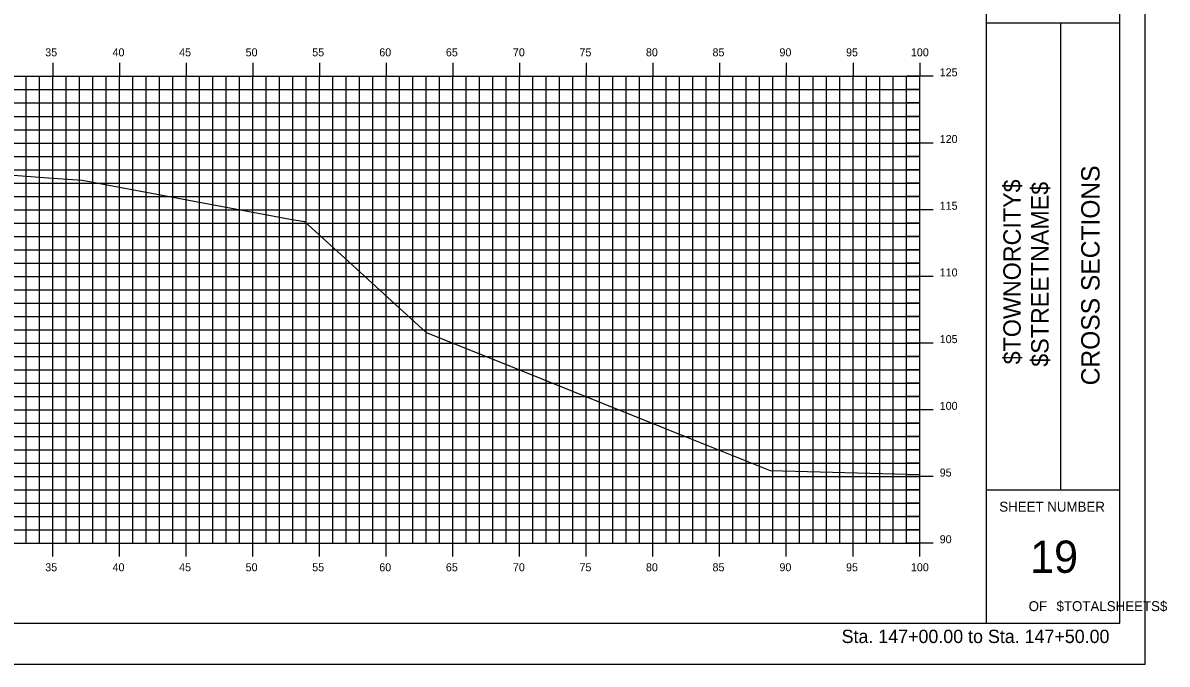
# Model space of a CAD drawing. Extents: x 850598 to 870284, y 366541 to 366651.
# Drawn here: x 850683.7 to 850769.4, y 366541.2 to 366589.2 of the extents above; entities that cross this region are included whole.
import ezdxf

# ---------------------------------------------------------------- set-up
doc = ezdxf.new("R2010")
doc.units = 0
for name, color, linetype in [('BORDER', 7, 'Continuous'), ('H_V ANNOTATION', 7, 'Continuous'), ('HIGHWAY_TITLE', 7, 'Continuous'), ('MAJOR', 7, 'Continuous'), ('MINOR', 7, 'Continuous'), ('PLOT BOUNDARY', 7, 'Continuous'), ('S_Roadway_Centerline', 7, 'Continuous')]:
    doc.layers.add(name, color=color, linetype=linetype)

msp = doc.modelspace()

# ---------------------------------------------------------------- linework, layer by layer
at = {"layer": 'BORDER'}
for p, q in [((850755.897, 366544.225), (850755.897, 366649.225)), ((850765.897, 366544.225), (850765.897, 366649.225)), ((850755.897, 366589.228), (850765.897, 366589.228)), ((850761.488, 366554.228), (850761.488, 366589.228)), ((850755.897, 366554.228), (850765.897, 366554.228)), ((850605.897, 366544.225), (850765.897, 366544.225))]:
    msp.add_line(p, q, dxfattribs=at)
at = {"layer": 'MAJOR'}
for p, q in [((850685.897, 366586.227), (850685.897, 366585.225)), ((850685.897, 366586.227), (850685.897, 366585.225)), ((850690.897, 366586.227), (850690.897, 366585.225)), ((850690.897, 366586.227), (850690.897, 366585.225)), ((850695.897, 366586.227), (850695.897, 366585.225)), ((850695.897, 366586.227), (850695.897, 366585.225)), ((850700.897, 366586.227), (850700.897, 366585.225)), ((850700.897, 366586.227), (850700.897, 366585.225)), ((850705.897, 366586.227), (850705.897, 366585.225)), ((850705.897, 366586.227), (850705.897, 366585.225)), ((850710.897, 366586.227), (850710.897, 366585.225)), ((850710.897, 366586.227), (850710.897, 366585.225)), ((850715.897, 366586.227), (850715.897, 366585.225)), ((850715.897, 366586.227), (850715.897, 366585.225)), ((850720.897, 366586.227), (850720.897, 366585.225)), ((850720.897, 366586.227), (850720.897, 366585.225)), ((850725.897, 366586.227), (850725.897, 366585.225)), ((850725.897, 366586.227), (850725.897, 366585.225)), ((850730.897, 366586.227), (850730.897, 366585.225)), ((850730.897, 366586.227), (850730.897, 366585.225)), ((850735.897, 366586.227), (850735.897, 366585.225)), ((850735.897, 366586.227), (850735.897, 366585.225)), ((850740.897, 366586.227), (850740.897, 366585.225)), ((850740.897, 366586.227), (850740.897, 366585.225)), ((850745.897, 366586.227), (850745.897, 366585.225)), ((850745.897, 366586.227), (850745.897, 366585.225)), ((850750.897, 366586.227), (850750.897, 366585.225)), ((850750.897, 366586.227), (850750.897, 366585.225)), ((850610.897, 366585.225), (850750.897, 366585.225)), ((850610.897, 366585.225), (850750.897, 366585.225)), ((850610.897, 366585.225), (850750.897, 366585.225)), ((850610.897, 366585.225), (850750.897, 366585.225)), ((850685.897, 366550.225), (850685.897, 366585.225)), ((850685.897, 366550.225), (850685.897, 366585.225)), ((850690.897, 366550.225), (850690.897, 366585.225)), ((850690.897, 366550.225), (850690.897, 366585.225)), ((850695.897, 366550.225), (850695.897, 366585.225)), ((850695.897, 366550.225), (850695.897, 366585.225)), ((850700.897, 366550.225), (850700.897, 366585.225)), ((850700.897, 366550.225), (850700.897, 366585.225)), ((850705.897, 366550.225), (850705.897, 366585.225)), ((850705.897, 366550.225), (850705.897, 366585.225)), ((850710.897, 366550.225), (850710.897, 366585.225)), ((850710.897, 366550.225), (850710.897, 366585.225)), ((850715.897, 366550.225), (850715.897, 366585.225)), ((850715.897, 366550.225), (850715.897, 366585.225)), ((850720.897, 366550.225), (850720.897, 366585.225)), ((850720.897, 366550.225), (850720.897, 366585.225)), ((850725.897, 366550.225), (850725.897, 366585.225)), ((850725.897, 366550.225), (850725.897, 366585.225)), ((850730.897, 366550.225), (850730.897, 366585.225)), ((850730.897, 366550.225), (850730.897, 366585.225)), ((850735.897, 366550.225), (850735.897, 366585.225)), ((850735.897, 366550.225), (850735.897, 366585.225)), ((850740.897, 366550.225), (850740.897, 366585.225)), ((850740.897, 366550.225), (850740.897, 366585.225)), ((850745.897, 366550.225), (850745.897, 366585.225)), ((850745.897, 366550.225), (850745.897, 366585.225)), ((850751.899, 366585.225), (850749.895, 366585.225)), ((850751.899, 366585.225), (850749.895, 366585.225)), ((850750.897, 366550.225), (850750.897, 366585.225)), ((850750.897, 366550.225), (850750.897, 366585.225)), ((850750.897, 366550.225), (850750.897, 366585.225)), ((850750.897, 366550.225), (850750.897, 366585.225)), ((850610.897, 366580.225), (850750.897, 366580.225)), ((850610.897, 366580.225), (850750.897, 366580.225)), ((850751.899, 366580.225), (850749.895, 366580.225)), ((850751.899, 366580.225), (850749.895, 366580.225)), ((850610.897, 366575.225), (850750.897, 366575.225)), ((850610.897, 366575.225), (850750.897, 366575.225)), ((850751.899, 366575.225), (850749.895, 366575.225)), ((850751.899, 366575.225), (850749.895, 366575.225)), ((850610.897, 366570.225), (850750.897, 366570.225)), ((850610.897, 366570.225), (850750.897, 366570.225)), ((850751.899, 366570.225), (850749.895, 366570.225)), ((850751.899, 366570.225), (850749.895, 366570.225)), ((850610.897, 366565.225), (850750.897, 366565.225)), ((850610.897, 366565.225), (850750.897, 366565.225)), ((850751.899, 366565.225), (850749.895, 366565.225)), ((850751.899, 366565.225), (850749.895, 366565.225)), ((850610.897, 366560.225), (850750.897, 366560.225)), ((850610.897, 366560.225), (850750.897, 366560.225)), ((850751.899, 366560.225), (850749.895, 366560.225)), ((850751.899, 366560.225), (850749.895, 366560.225)), ((850610.897, 366555.225), (850750.897, 366555.225)), ((850610.897, 366555.225), (850750.897, 366555.225)), ((850751.899, 366555.225), (850749.895, 366555.225)), ((850751.899, 366555.225), (850749.895, 366555.225)), ((850610.897, 366550.225), (850750.897, 366550.225)), ((850610.897, 366550.225), (850750.897, 366550.225)), ((850610.897, 366550.225), (850750.897, 366550.225)), ((850610.897, 366550.225), (850750.897, 366550.225)), ((850685.897, 366549.223), (850685.897, 366550.225)), ((850685.897, 366549.223), (850685.897, 366550.225)), ((850690.897, 366549.223), (850690.897, 366550.225)), ((850690.897, 366549.223), (850690.897, 366550.225)), ((850695.897, 366549.223), (850695.897, 366550.225)), ((850695.897, 366549.223), (850695.897, 366550.225)), ((850700.897, 366549.223), (850700.897, 366550.225)), ((850700.897, 366549.223), (850700.897, 366550.225)), ((850705.897, 366549.223), (850705.897, 366550.225)), ((850705.897, 366549.223), (850705.897, 366550.225)), ((850710.897, 366549.223), (850710.897, 366550.225)), ((850710.897, 366549.223), (850710.897, 366550.225)), ((850715.897, 366549.223), (850715.897, 366550.225)), ((850715.897, 366549.223), (850715.897, 366550.225)), ((850720.897, 366549.223), (850720.897, 366550.225)), ((850720.897, 366549.223), (850720.897, 366550.225)), ((850725.897, 366549.223), (850725.897, 366550.225)), ((850725.897, 366549.223), (850725.897, 366550.225)), ((850730.897, 366549.223), (850730.897, 366550.225)), ((850730.897, 366549.223), (850730.897, 366550.225)), ((850735.897, 366549.223), (850735.897, 366550.225)), ((850735.897, 366549.223), (850735.897, 366550.225)), ((850740.897, 366549.223), (850740.897, 366550.225)), ((850740.897, 366549.223), (850740.897, 366550.225)), ((850745.897, 366549.223), (850745.897, 366550.225)), ((850745.897, 366549.223), (850745.897, 366550.225)), ((850751.899, 366550.225), (850749.895, 366550.225)), ((850751.899, 366550.225), (850749.895, 366550.225)), ((850750.897, 366549.223), (850750.897, 366550.225)), ((850750.897, 366549.223), (850750.897, 366550.225))]:
    msp.add_line(p, q, dxfattribs=at)
at = {"layer": 'MINOR'}
for p, q in [((850683.897, 366550.225), (850683.897, 366585.225)), ((850683.897, 366550.225), (850683.897, 366585.225)), ((850684.897, 366550.225), (850684.897, 366585.225)), ((850684.897, 366550.225), (850684.897, 366585.225)), ((850686.897, 366550.225), (850686.897, 366585.225)), ((850686.897, 366550.225), (850686.897, 366585.225)), ((850687.897, 366550.225), (850687.897, 366585.225)), ((850687.897, 366550.225), (850687.897, 366585.225)), ((850688.897, 366550.225), (850688.897, 366585.225)), ((850688.897, 366550.225), (850688.897, 366585.225)), ((850689.897, 366550.225), (850689.897, 366585.225)), ((850689.897, 366550.225), (850689.897, 366585.225)), ((850691.897, 366550.225), (850691.897, 366585.225)), ((850691.897, 366550.225), (850691.897, 366585.225)), ((850692.897, 366550.225), (850692.897, 366585.225)), ((850692.897, 366550.225), (850692.897, 366585.225)), ((850693.897, 366550.225), (850693.897, 366585.225)), ((850693.897, 366550.225), (850693.897, 366585.225)), ((850694.897, 366550.225), (850694.897, 366585.225)), ((850694.897, 366550.225), (850694.897, 366585.225)), ((850696.897, 366550.225), (850696.897, 366585.225)), ((850696.897, 366550.225), (850696.897, 366585.225)), ((850697.897, 366550.225), (850697.897, 366585.225)), ((850697.897, 366550.225), (850697.897, 366585.225)), ((850698.897, 366550.225), (850698.897, 366585.225)), ((850698.897, 366550.225), (850698.897, 366585.225)), ((850699.897, 366550.225), (850699.897, 366585.225)), ((850699.897, 366550.225), (850699.897, 366585.225)), ((850701.897, 366550.225), (850701.897, 366585.225)), ((850701.897, 366550.225), (850701.897, 366585.225)), ((850702.897, 366550.225), (850702.897, 366585.225)), ((850702.897, 366550.225), (850702.897, 366585.225)), ((850703.897, 366550.225), (850703.897, 366585.225)), ((850703.897, 366550.225), (850703.897, 366585.225)), ((850704.897, 366550.225), (850704.897, 366585.225)), ((850704.897, 366550.225), (850704.897, 366585.225)), ((850706.897, 366550.225), (850706.897, 366585.225)), ((850706.897, 366550.225), (850706.897, 366585.225)), ((850707.897, 366550.225), (850707.897, 366585.225)), ((850707.897, 366550.225), (850707.897, 366585.225)), ((850708.897, 366550.225), (850708.897, 366585.225)), ((850708.897, 366550.225), (850708.897, 366585.225)), ((850709.897, 366550.225), (850709.897, 366585.225)), ((850709.897, 366550.225), (850709.897, 366585.225)), ((850711.897, 366550.225), (850711.897, 366585.225)), ((850711.897, 366550.225), (850711.897, 366585.225)), ((850712.897, 366550.225), (850712.897, 366585.225)), ((850712.897, 366550.225), (850712.897, 366585.225)), ((850713.897, 366550.225), (850713.897, 366585.225)), ((850713.897, 366550.225), (850713.897, 366585.225)), ((850714.897, 366550.225), (850714.897, 366585.225)), ((850714.897, 366550.225), (850714.897, 366585.225)), ((850716.897, 366550.225), (850716.897, 366585.225)), ((850716.897, 366550.225), (850716.897, 366585.225)), ((850717.897, 366550.225), (850717.897, 366585.225)), ((850717.897, 366550.225), (850717.897, 366585.225)), ((850718.897, 366550.225), (850718.897, 366585.225)), ((850718.897, 366550.225), (850718.897, 366585.225)), ((850719.897, 366550.225), (850719.897, 366585.225)), ((850719.897, 366550.225), (850719.897, 366585.225)), ((850721.897, 366550.225), (850721.897, 366585.225)), ((850721.897, 366550.225), (850721.897, 366585.225)), ((850722.897, 366550.225), (850722.897, 366585.225)), ((850722.897, 366550.225), (850722.897, 366585.225)), ((850723.897, 366550.225), (850723.897, 366585.225)), ((850723.897, 366550.225), (850723.897, 366585.225)), ((850724.897, 366550.225), (850724.897, 366585.225)), ((850724.897, 366550.225), (850724.897, 366585.225)), ((850726.897, 366550.225), (850726.897, 366585.225)), ((850726.897, 366550.225), (850726.897, 366585.225)), ((850727.897, 366550.225), (850727.897, 366585.225)), ((850727.897, 366550.225), (850727.897, 366585.225)), ((850728.897, 366550.225), (850728.897, 366585.225)), ((850728.897, 366550.225), (850728.897, 366585.225)), ((850729.897, 366550.225), (850729.897, 366585.225)), ((850729.897, 366550.225), (850729.897, 366585.225)), ((850731.897, 366550.225), (850731.897, 366585.225)), ((850731.897, 366550.225), (850731.897, 366585.225)), ((850732.897, 366550.225), (850732.897, 366585.225)), ((850732.897, 366550.225), (850732.897, 366585.225)), ((850733.897, 366550.225), (850733.897, 366585.225)), ((850733.897, 366550.225), (850733.897, 366585.225)), ((850734.897, 366550.225), (850734.897, 366585.225)), ((850734.897, 366550.225), (850734.897, 366585.225)), ((850736.897, 366550.225), (850736.897, 366585.225)), ((850736.897, 366550.225), (850736.897, 366585.225)), ((850737.897, 366550.225), (850737.897, 366585.225)), ((850737.897, 366550.225), (850737.897, 366585.225)), ((850738.897, 366550.225), (850738.897, 366585.225)), ((850738.897, 366550.225), (850738.897, 366585.225)), ((850739.897, 366550.225), (850739.897, 366585.225)), ((850739.897, 366550.225), (850739.897, 366585.225)), ((850741.897, 366550.225), (850741.897, 366585.225)), ((850741.897, 366550.225), (850741.897, 366585.225)), ((850742.897, 366550.225), (850742.897, 366585.225)), ((850742.897, 366550.225), (850742.897, 366585.225)), ((850743.897, 366550.225), (850743.897, 366585.225)), ((850743.897, 366550.225), (850743.897, 366585.225)), ((850744.897, 366550.225), (850744.897, 366585.225)), ((850744.897, 366550.225), (850744.897, 366585.225)), ((850746.897, 366550.225), (850746.897, 366585.225)), ((850746.897, 366550.225), (850746.897, 366585.225)), ((850747.897, 366550.225), (850747.897, 366585.225)), ((850747.897, 366550.225), (850747.897, 366585.225)), ((850748.897, 366550.225), (850748.897, 366585.225)), ((850748.897, 366550.225), (850748.897, 366585.225)), ((850749.897, 366550.225), (850749.897, 366585.225)), ((850749.897, 366550.225), (850749.897, 366585.225)), ((850610.897, 366584.225), (850750.897, 366584.225)), ((850610.897, 366584.225), (850750.897, 366584.225)), ((850750.897, 366584.225), (850749.895, 366584.225)), ((850750.897, 366584.225), (850749.895, 366584.225)), ((850610.897, 366583.225), (850750.897, 366583.225)), ((850610.897, 366583.225), (850750.897, 366583.225)), ((850750.897, 366583.225), (850749.895, 366583.225)), ((850750.897, 366583.225), (850749.895, 366583.225)), ((850610.897, 366582.225), (850750.897, 366582.225)), ((850610.897, 366582.225), (850750.897, 366582.225)), ((850750.897, 366582.225), (850749.895, 366582.225)), ((850750.897, 366582.225), (850749.895, 366582.225)), ((850610.897, 366581.225), (850750.897, 366581.225)), ((850610.897, 366581.225), (850750.897, 366581.225)), ((850750.897, 366581.225), (850749.895, 366581.225)), ((850750.897, 366581.225), (850749.895, 366581.225)), ((850610.897, 366579.225), (850750.897, 366579.225)), ((850610.897, 366579.225), (850750.897, 366579.225)), ((850750.897, 366579.225), (850749.895, 366579.225)), ((850750.897, 366579.225), (850749.895, 366579.225)), ((850610.897, 366578.225), (850750.897, 366578.225)), ((850610.897, 366578.225), (850750.897, 366578.225)), ((850750.897, 366578.225), (850749.895, 366578.225)), ((850750.897, 366578.225), (850749.895, 366578.225)), ((850610.897, 366577.225), (850750.897, 366577.225)), ((850610.897, 366577.225), (850750.897, 366577.225)), ((850750.897, 366577.225), (850749.895, 366577.225)), ((850750.897, 366577.225), (850749.895, 366577.225)), ((850610.897, 366576.225), (850750.897, 366576.225)), ((850610.897, 366576.225), (850750.897, 366576.225)), ((850750.897, 366576.225), (850749.895, 366576.225)), ((850750.897, 366576.225), (850749.895, 366576.225)), ((850610.897, 366574.225), (850750.897, 366574.225)), ((850610.897, 366574.225), (850750.897, 366574.225)), ((850750.897, 366574.225), (850749.895, 366574.225)), ((850750.897, 366574.225), (850749.895, 366574.225)), ((850610.897, 366573.225), (850750.897, 366573.225)), ((850610.897, 366573.225), (850750.897, 366573.225)), ((850750.897, 366573.225), (850749.895, 366573.225)), ((850750.897, 366573.225), (850749.895, 366573.225)), ((850610.897, 366572.225), (850750.897, 366572.225)), ((850610.897, 366572.225), (850750.897, 366572.225)), ((850750.897, 366572.225), (850749.895, 366572.225)), ((850750.897, 366572.225), (850749.895, 366572.225)), ((850610.897, 366571.225), (850750.897, 366571.225)), ((850610.897, 366571.225), (850750.897, 366571.225)), ((850750.897, 366571.225), (850749.895, 366571.225)), ((850750.897, 366571.225), (850749.895, 366571.225)), ((850610.897, 366569.225), (850750.897, 366569.225)), ((850610.897, 366569.225), (850750.897, 366569.225)), ((850750.897, 366569.225), (850749.895, 366569.225)), ((850750.897, 366569.225), (850749.895, 366569.225)), ((850610.897, 366568.225), (850750.897, 366568.225)), ((850610.897, 366568.225), (850750.897, 366568.225)), ((850750.897, 366568.225), (850749.895, 366568.225)), ((850750.897, 366568.225), (850749.895, 366568.225)), ((850610.897, 366567.225), (850750.897, 366567.225)), ((850610.897, 366567.225), (850750.897, 366567.225)), ((850750.897, 366567.225), (850749.895, 366567.225)), ((850750.897, 366567.225), (850749.895, 366567.225)), ((850610.897, 366566.225), (850750.897, 366566.225)), ((850610.897, 366566.225), (850750.897, 366566.225)), ((850750.897, 366566.225), (850749.895, 366566.225)), ((850750.897, 366566.225), (850749.895, 366566.225)), ((850610.897, 366564.225), (850750.897, 366564.225)), ((850610.897, 366564.225), (850750.897, 366564.225)), ((850750.897, 366564.225), (850749.895, 366564.225)), ((850750.897, 366564.225), (850749.895, 366564.225)), ((850610.897, 366563.225), (850750.897, 366563.225)), ((850610.897, 366563.225), (850750.897, 366563.225)), ((850750.897, 366563.225), (850749.895, 366563.225)), ((850750.897, 366563.225), (850749.895, 366563.225)), ((850610.897, 366562.225), (850750.897, 366562.225)), ((850610.897, 366562.225), (850750.897, 366562.225)), ((850750.897, 366562.225), (850749.895, 366562.225)), ((850750.897, 366562.225), (850749.895, 366562.225)), ((850610.897, 366561.225), (850750.897, 366561.225)), ((850610.897, 366561.225), (850750.897, 366561.225)), ((850750.897, 366561.225), (850749.895, 366561.225)), ((850750.897, 366561.225), (850749.895, 366561.225)), ((850610.897, 366559.225), (850750.897, 366559.225)), ((850610.897, 366559.225), (850750.897, 366559.225)), ((850750.897, 366559.225), (850749.895, 366559.225)), ((850750.897, 366559.225), (850749.895, 366559.225)), ((850610.897, 366558.225), (850750.897, 366558.225)), ((850610.897, 366558.225), (850750.897, 366558.225)), ((850750.897, 366558.225), (850749.895, 366558.225)), ((850750.897, 366558.225), (850749.895, 366558.225)), ((850610.897, 366557.225), (850750.897, 366557.225)), ((850610.897, 366557.225), (850750.897, 366557.225)), ((850750.897, 366557.225), (850749.895, 366557.225)), ((850750.897, 366557.225), (850749.895, 366557.225)), ((850610.897, 366556.225), (850750.897, 366556.225)), ((850610.897, 366556.225), (850750.897, 366556.225)), ((850750.897, 366556.225), (850749.895, 366556.225)), ((850750.897, 366556.225), (850749.895, 366556.225)), ((850610.897, 366554.225), (850750.897, 366554.225)), ((850610.897, 366554.225), (850750.897, 366554.225)), ((850750.897, 366554.225), (850749.895, 366554.225)), ((850750.897, 366554.225), (850749.895, 366554.225)), ((850610.897, 366553.225), (850750.897, 366553.225)), ((850610.897, 366553.225), (850750.897, 366553.225)), ((850750.897, 366553.225), (850749.895, 366553.225)), ((850750.897, 366553.225), (850749.895, 366553.225)), ((850610.897, 366552.225), (850750.897, 366552.225)), ((850610.897, 366552.225), (850750.897, 366552.225)), ((850750.897, 366552.225), (850749.895, 366552.225)), ((850750.897, 366552.225), (850749.895, 366552.225)), ((850610.897, 366551.225), (850750.897, 366551.225)), ((850610.897, 366551.225), (850750.897, 366551.225)), ((850750.897, 366551.225), (850749.895, 366551.225)), ((850750.897, 366551.225), (850749.895, 366551.225))]:
    msp.add_line(p, q, dxfattribs=at)
at = {"layer": 'PLOT BOUNDARY'}
msp.add_lwpolyline([(850597.804, 366541.166), (850767.804, 366541.166), (850767.804, 366651.166), (850597.804, 366651.166)], close=True, dxfattribs=at)
at = {"layer": 'S_Roadway_Centerline'}
msp.add_lwpolyline([(850682.961, 366577.809), (850685.235, 366577.644), (850688.114, 366577.43), (850703.688, 366574.518), (850704.772, 366574.341), (850707.219, 366572.128), (850713.884, 366566.022), (850718.339, 366564.24), (850733.676, 366558.079), (850739.684, 366555.69), (850750.897, 366555.374)], dxfattribs=at)

# ---------------------------------------------------------------- texts
at = {"layer": 'BORDER'}
for s, height, rotation, p in [('CROSS SECTIONS', 1.37787, 90, (850764.382, 366562.062)), ('SHEET NUMBER', 0.74527, 360, (850756.863, 366552.592)), ('19', 2.4194, 360, (850759.169, 366548.008)), ('OF', 0.7453, 360, (850759.064, 366545.138)), ('$TOTALSHEETS$', 0.74527, 360, (850761.154, 366545.138))]:
    msp.add_text(s, height=height, rotation=rotation, dxfattribs=at).set_placement(p)
at = {"layer": 'H_V ANNOTATION'}
for s, height, p in [('35', 0.6, (850685.338, 366586.725)), ('40', 0.6, (850690.383, 366586.725)), ('45', 0.6, (850695.375, 366586.725)), ('50', 0.6, (850700.362, 366586.725)), ('55', 0.6, (850705.354, 366586.725)), ('60', 0.6, (850710.383, 366586.725)), ('65', 0.6, (850715.375, 366586.725)), ('70', 0.6, (850720.399, 366586.725)), ('75', 0.6, (850725.391, 366586.725)), ('80', 0.6, (850730.372, 366586.725)), ('85', 0.6, (850735.364, 366586.725)), ('90', 0.6, (850740.383, 366586.725)), ('95', 0.6, (850745.375, 366586.725)), ('100', 0.6, (850750.239, 366586.725)), ('125', 0.6, (850752.397, 366585.225)), ('120', 0.6, (850752.397, 366580.225)), ('115', 0.6, (850752.397, 366575.225)), ('110', 0.6, (850752.397, 366570.225)), ('105', 0.6, (850752.397, 366565.225)), ('100', 0.6, (850752.397, 366560.225)), ('95', 0.6, (850752.397, 366555.225)), ('90', 0.6, (850752.397, 366550.225)), ('35', 0.6, (850685.338, 366548.125)), ('40', 0.6, (850690.383, 366548.125)), ('45', 0.6, (850695.375, 366548.125)), ('50', 0.6, (850700.362, 366548.125)), ('55', 0.6, (850705.354, 366548.125)), ('60', 0.6, (850710.383, 366548.125)), ('65', 0.6, (850715.375, 366548.125)), ('70', 0.6, (850720.399, 366548.125)), ('75', 0.6, (850725.391, 366548.125)), ('80', 0.6, (850730.372, 366548.125)), ('85', 0.6, (850735.364, 366548.125)), ('90', 0.6, (850740.383, 366548.125)), ('95', 0.6, (850745.375, 366548.125)), ('100', 0.6, (850750.239, 366548.125)), ('Sta. 147+00.00 to Sta. 147+50.00', 1.0002, (850745.043, 366542.745))]:
    msp.add_text(s, height=height, dxfattribs=at).set_placement(p)
at = {"layer": 'HIGHWAY_TITLE'}
for s, p in [('$TOWNORCITY$', (850758.469, 366563.637)), ('$STREETNAME$', (850760.556, 366563.457))]:
    msp.add_text(s, height=1.30428, rotation=90, dxfattribs=at).set_placement(p)

doc.saveas('drawing.dxf')
